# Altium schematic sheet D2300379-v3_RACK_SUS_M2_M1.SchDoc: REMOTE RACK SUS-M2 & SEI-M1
size C; Engineer: L. Sanchez; Organization: LIGO Laboratory; Address1: California Institute of Technology; Address2: Massachusetts Institute of Technology; DocumentNumber: D2300379; Revision: v2; SheetNumber: 9; SheetTotal: 9
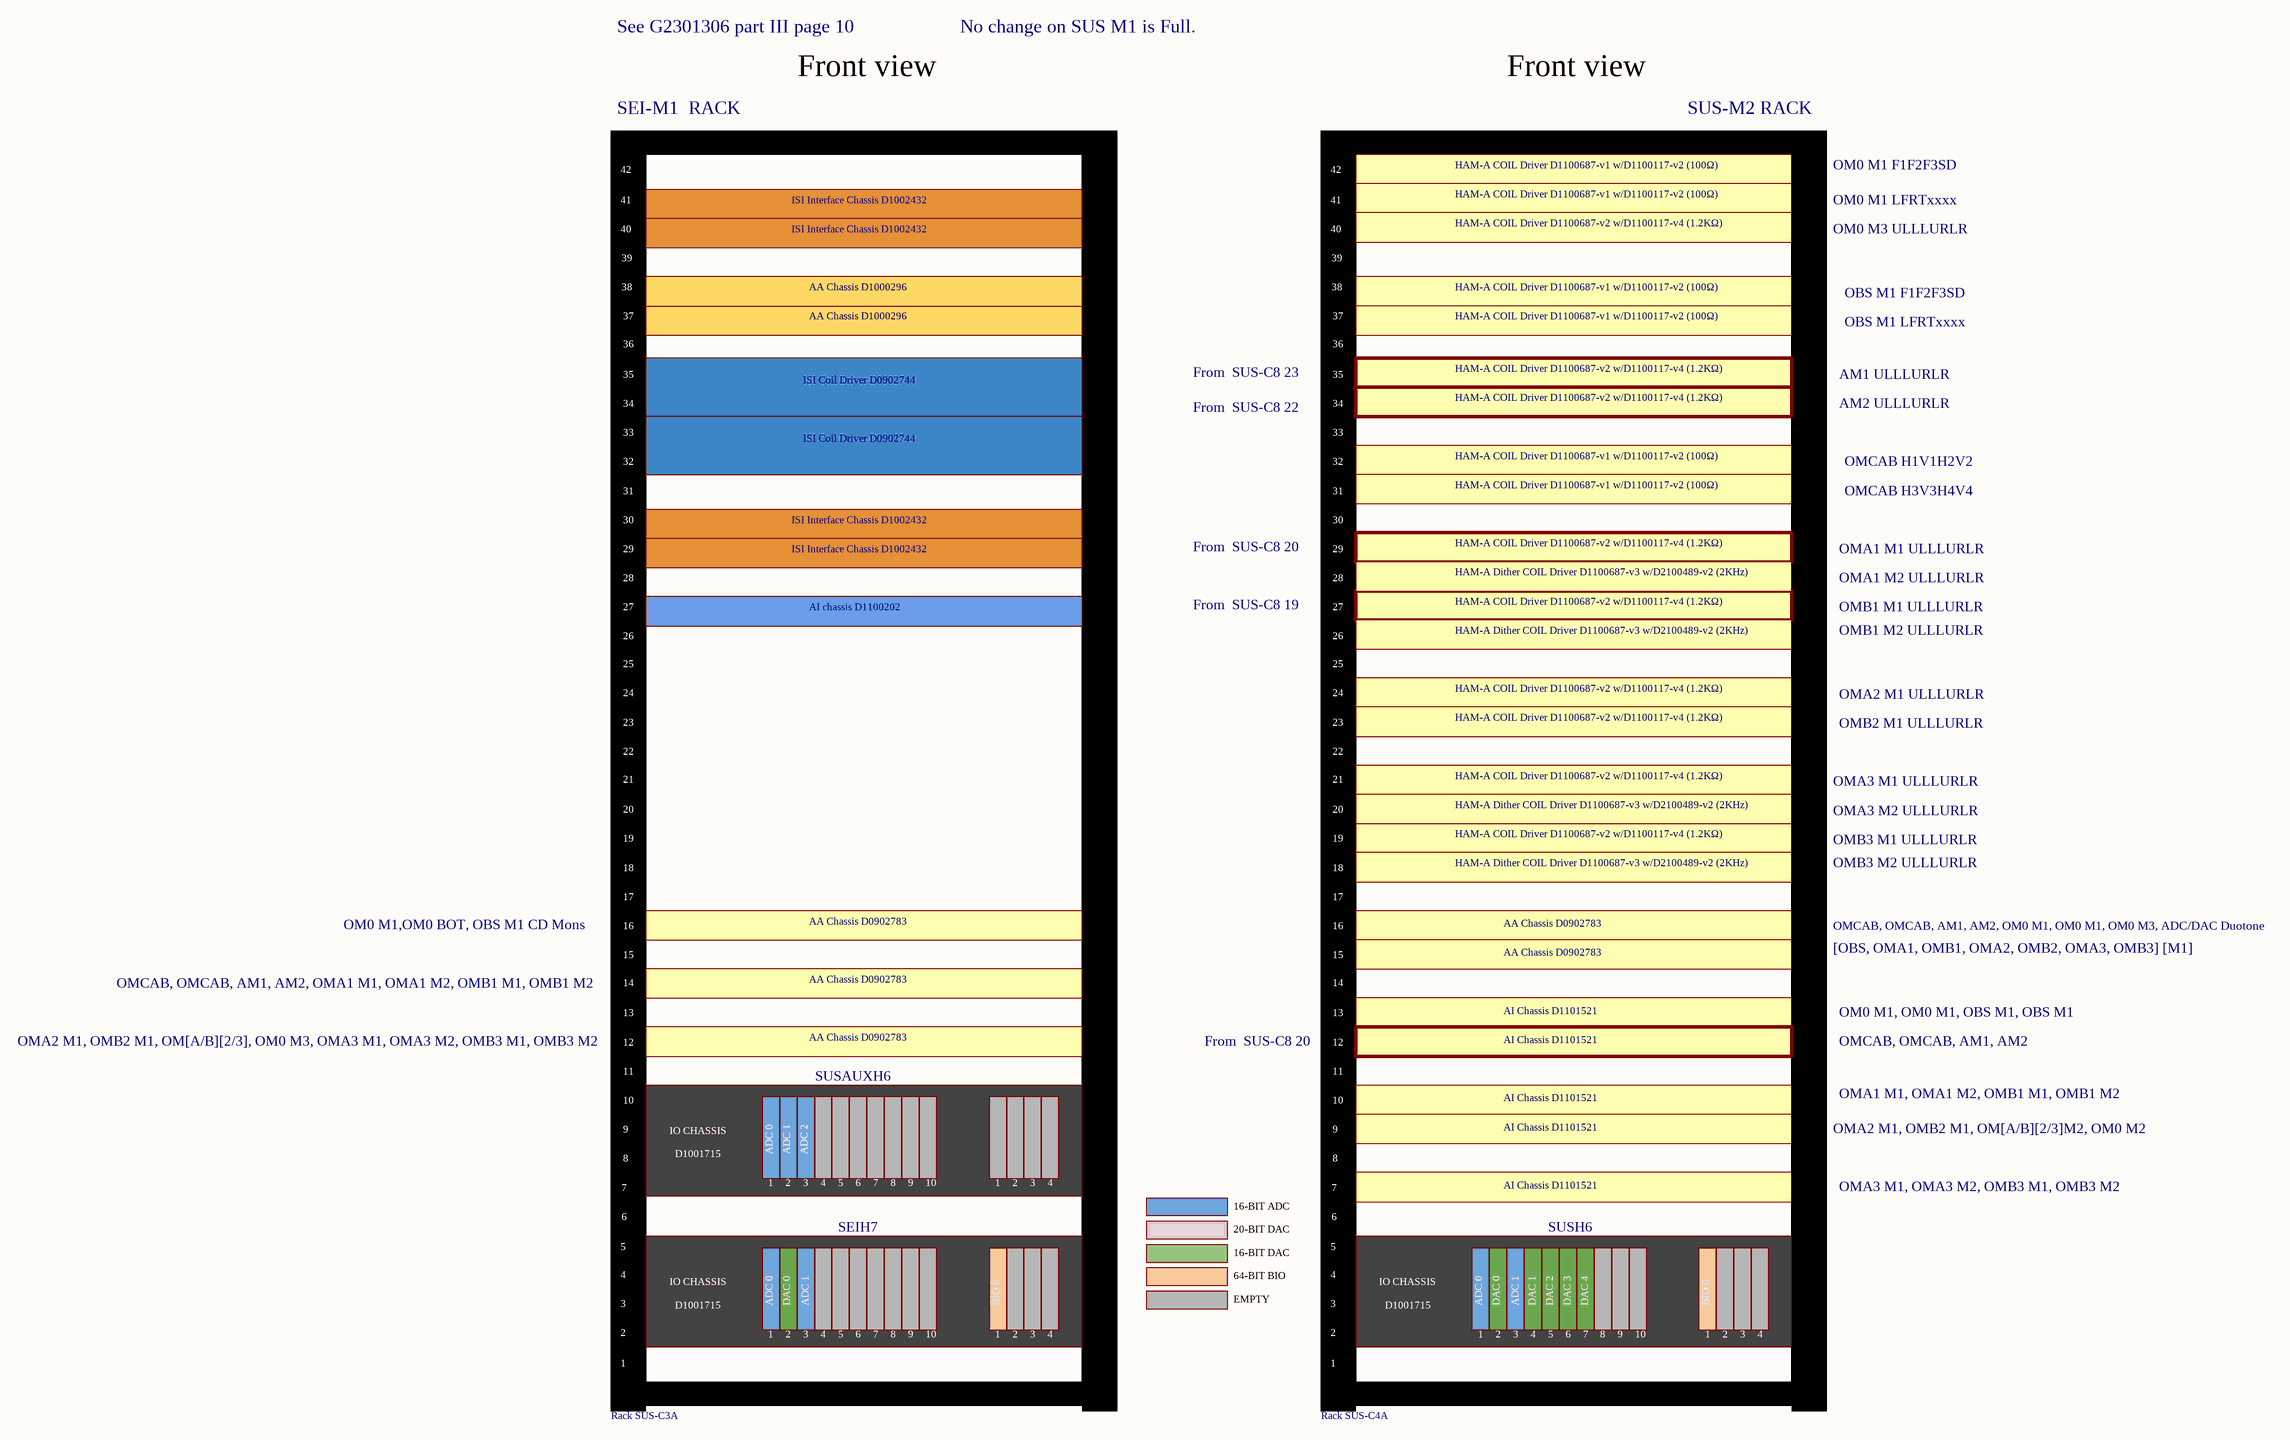
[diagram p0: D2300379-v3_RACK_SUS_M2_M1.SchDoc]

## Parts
Rack_SUS-C3  1U  Rack 42 pos  (value not drawn)  (part A of 2)
Rack_SUS-C4  1U  Rack 42 pos  (value not drawn)  (part A of 2)

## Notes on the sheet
- See G2301306 part III page 10
- No change on SUS M1 is Full.
- Front view
- SEI-M1  RACK
- SUS-M2 RACK
- OM0 M1 F1F2F3SD
- ISI Interface Chassis D1002432
- HAM-A COIL Driver D1100687-v1 w/D1100117-v2 (100Ω)
- OM0 M3 ULLLURLR
- OM0 M1 LFRTxxxx
- HAM-A COIL Driver D1100687-v2 w/D1100117-v4 (1.2KΩ)
- OBS M1 F1F2F3SD
- AA Chassis D1000296
- OBS M1 LFRTxxxx
- ISI Coil Driver D0902744
- From  SUS-C8 23
- AM2 ULLLURLR
- AM1 ULLLURLR
- From  SUS-C8 22
- OMCAB H1V1H2V2
- OMCAB H3V3H4V4
- From  SUS-C8 20
- OMA1 M1 ULLLURLR
- OMA1 M2 ULLLURLR
- AI chassis D1100202
- From  SUS-C8 19
- HAM-A Dither COIL Driver D1100687-v3 w/D2100489-v2 (2KHz)
- OMB1 M1 ULLLURLR
- OMB1 M2 ULLLURLR
- OMA2 M1 ULLLURLR
- OMB2 M1 ULLLURLR
- (near Rack_SUS-C4) HAM-A COIL Driver D1100687-v2 w/D1100117-v4 (1.2KΩ)
- OMA3 M2 ULLLURLR
- OMA3 M1 ULLLURLR
- (near Rack_SUS-C4) HAM-A Dither COIL Driver D1100687-v3 w/D2100489-v2 (2KHz)
- OMB3 M2 ULLLURLR
- OMB3 M1 ULLLURLR
- OM0 M1,OM0 BOT, OBS M1 CD Mons
- AA Chassis D0902783
- [OBS, OMA1, OMB1, OMA2, OMB2, OMA3, OMB3] [M1]
- OMCAB, OMCAB, AM1, AM2, OM0 M1, OM0 M1, OM0 M3, ADC/DAC Duotone
- OMCAB, OMCAB, AM1, AM2, OMA1 M1, OMA1 M2, OMB1 M1, OMB1 M2
- AI Chassis D1101521
- OM0 M1, OM0 M1, OBS M1, OBS M1
- OMA2 M1, OMB2 M1, OM[A/B][2/3], OM0 M3, OMA3 M1, OMA3 M2, OMB3 M1, OMB3 M2
- SUSAUXH6
- OMCAB, OMCAB, AM1, AM2
- IO CHASSIS
- OMA2 M1, OMB2 M1, OM[A/B][2/3]M2, OM0 M2
- OMA1 M1, OMA1 M2, OMB1 M1, OMB1 M2
- D1001715
- 1
- ADC 0
- 2
- ADC 1
- 3
- ADC 2
- 4
- 5
- 6
- 7
- 8
- 9
- 10
- 16-BIT ADC
- OMA3 M1, OMA3 M2, OMB3 M1, OMB3 M2
- SEIH7
- 20-BIT DAC
- 16-BIT DAC
- SUSH6
- DAC 0
- BIO 0
- 64-BIT BIO
- EMPTY
- DAC 1
- DAC 2
- DAC 3
- DAC 4

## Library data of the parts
Rack_SUS-C3 Rack_SUS-C4 = RACK_42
